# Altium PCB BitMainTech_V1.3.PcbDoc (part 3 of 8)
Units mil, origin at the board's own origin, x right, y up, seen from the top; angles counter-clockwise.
Board outline 9842.52 x 6082.68 mil, 4 copper layers (Top Layer, Mid-Layer 1, Mid-Layer 2, Bottom Layer); 987 components, 282 nets, 3694 pads, 3174 vias.
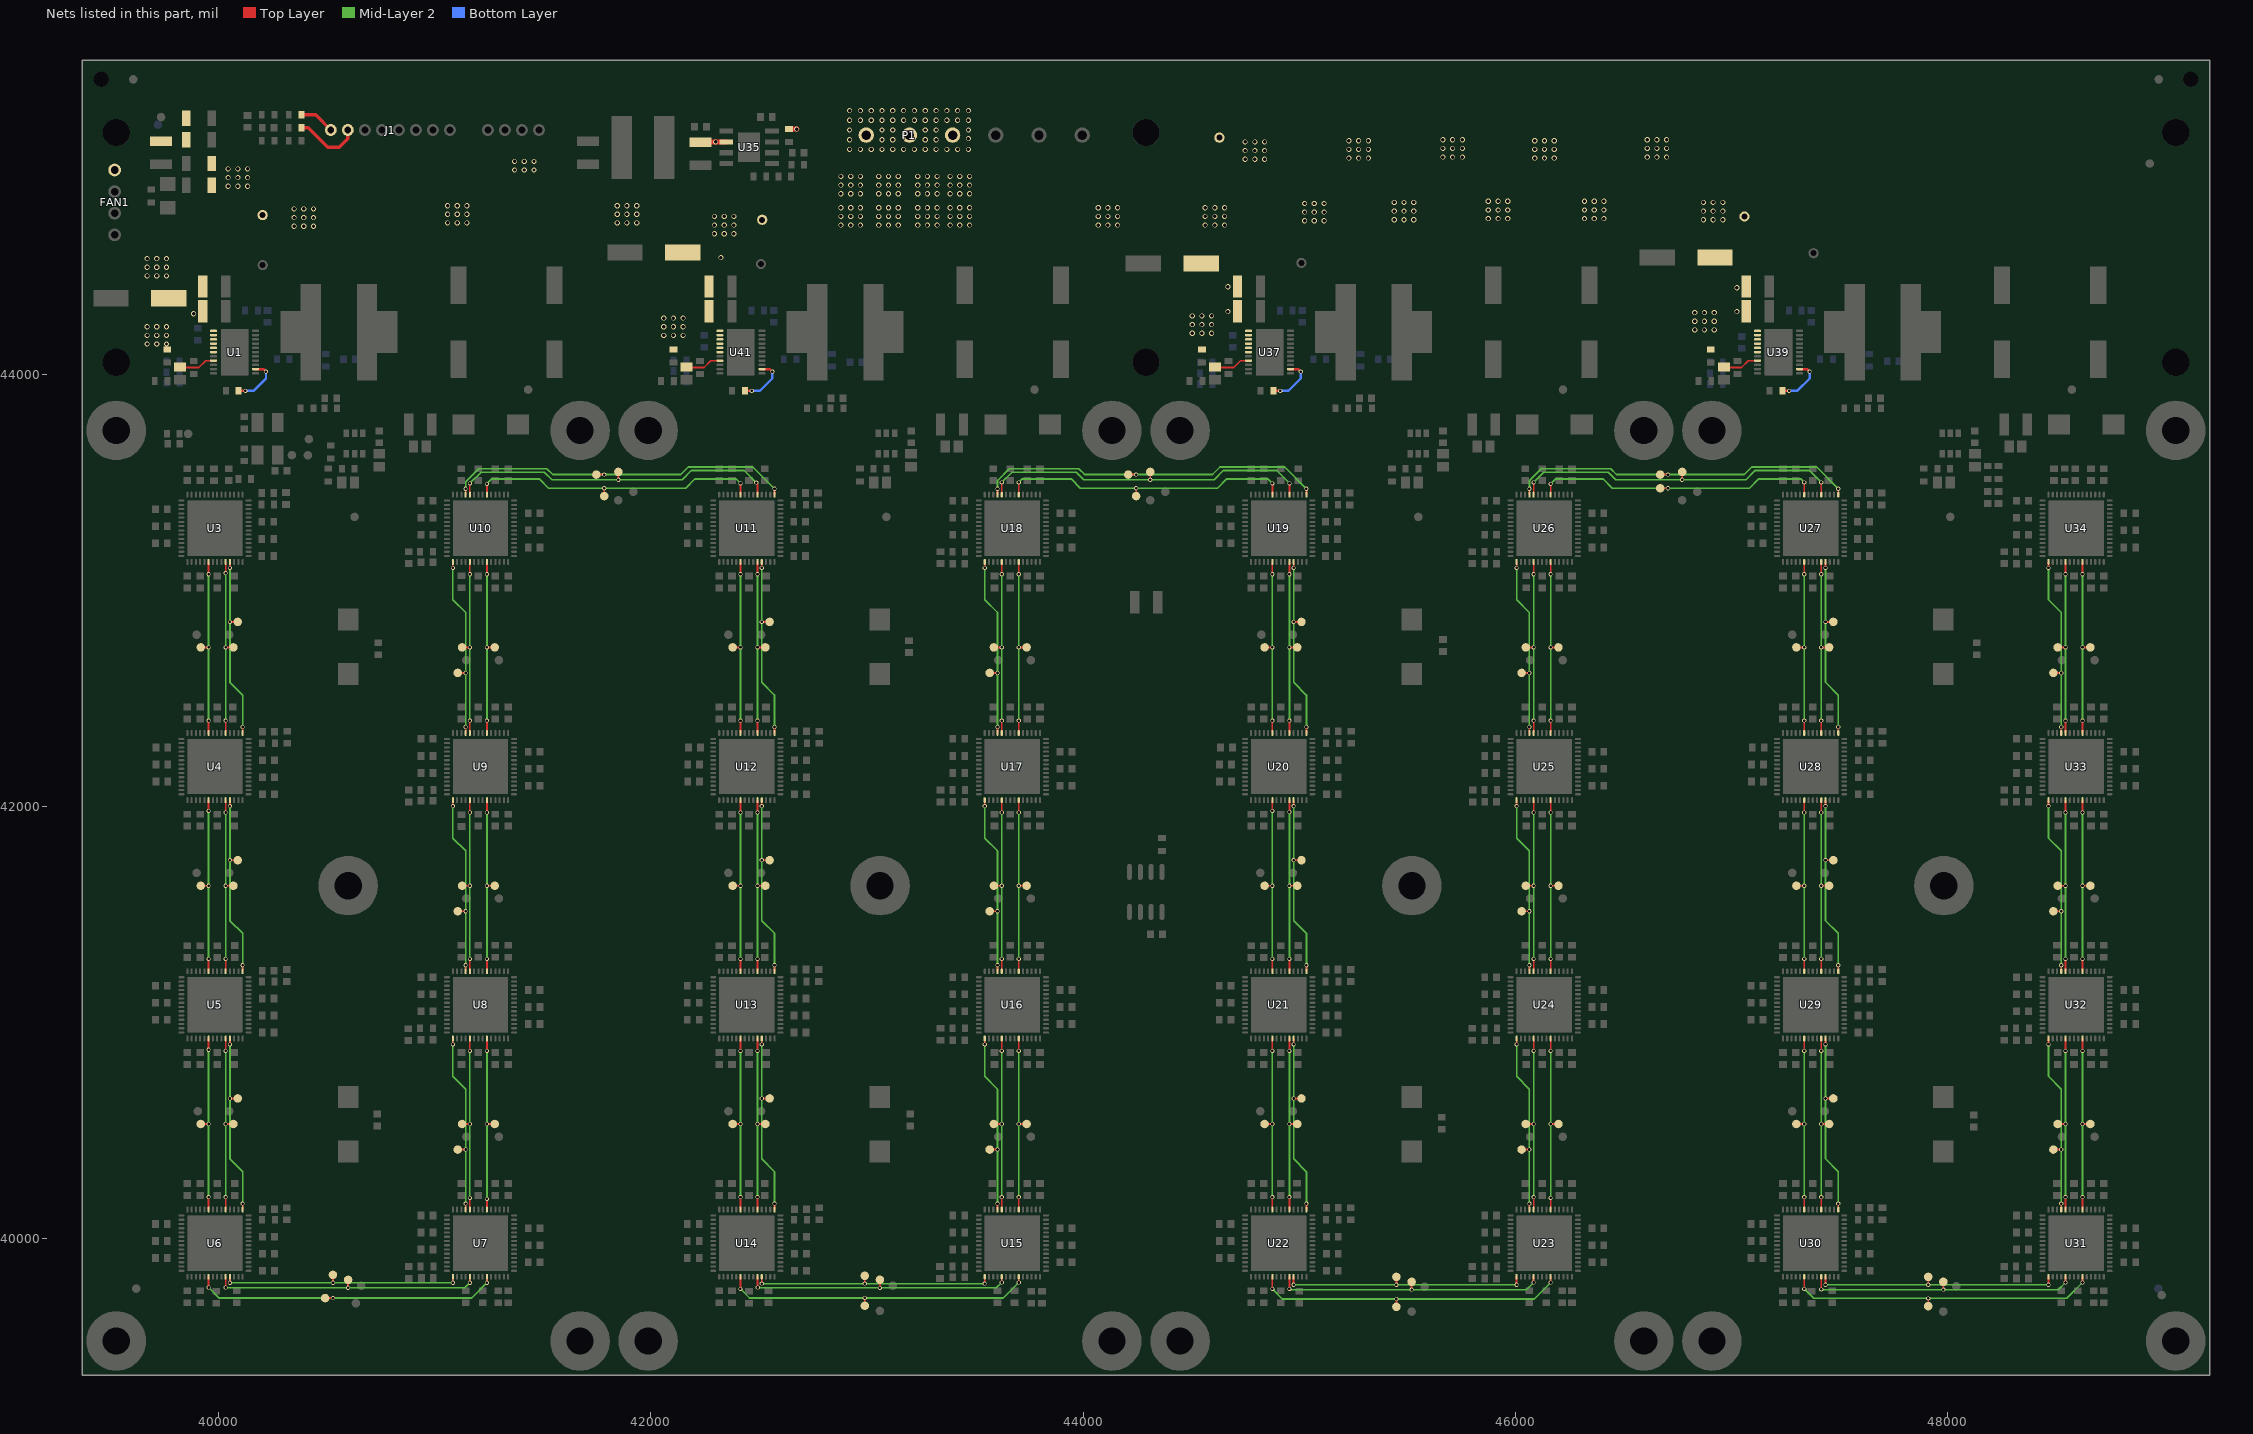
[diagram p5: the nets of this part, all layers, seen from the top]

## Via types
v1: diameter 19, hole 12, Top Layer to Bottom Layer, 1347 vias
v2: diameter 25.98, hole 12.99, Top Layer to Bottom Layer, 800 vias
v3: diameter 24, hole 16, Top Layer to Bottom Layer, 778 vias
v4: diameter 50, hole 28, Top Layer to Bottom Layer, 160 vias
v5: diameter 19.68, hole 11.81, Top Layer to Bottom Layer, 84 vias
v6: diameter 26, hole 18, Top Layer to Bottom Layer, 5 vias

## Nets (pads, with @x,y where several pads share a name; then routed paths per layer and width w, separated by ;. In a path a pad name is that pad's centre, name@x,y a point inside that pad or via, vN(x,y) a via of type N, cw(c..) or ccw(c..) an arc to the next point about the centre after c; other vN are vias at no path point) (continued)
+12V: C5.1 C6.1 C7.1 C548.2 C553.1 C554.1 C568.1 C569.1 C570.1 C584.1 C585.1 C586.1 C600.1 C606.1 C607.1 C608.1 C609.1 FB33.2 FB34.2 P1.1 P1.2 P1.3 R2.1 R22.2 R37.1 R51.1 R65.1 TP2.1 TP165.1 TP169.1 TP173.1 U1.12 U1.13 U1.14 U1.15 U1.16 U1.17 U1.19 U35.2 U37.12 U37.13 U37.14 U37.15 U37.16 U37.17 U37.19 U39.12 U39.13 U39.14 U39.15 U39.16 U39.17 U39.19 U41.12 U41.13 U41.14 U41.15 U41.16 U41.17 U41.19 | length 821.5
  Top Layer w8: C7.1@39822.83,44031.5 39909.5,44031.5 39940.99,44062.99 U1.19@39977.56,44062.99 ; C554.1@42165.35,44031.5 42246.58,44031.5 ; 42246.54,44031.54 42277.99,44062.99 U41.19@42320.08,44062.99 ; C570.1@44610.24,44031.5 44696.9,44031.5 44728.39,44062.99 U37.19@44764.96,44062.99 ; C586.1@46964.57,44031.5 47046.5,44031.5 47077.99,44062.99 U39.19@47119.29,44062.99
  Top Layer w24: C548.2@42232.09,45075 U35.2@42347.48,45075
  Top Layer w25: R22.2@42640,45134.53 v3(42675,45134.53)
  other v3: 39670,44140 39715,44140 39760,44140 39670,44180 39715,44180 39760,44180 42060,44180 42105,44180 42150,44180 44505,44190 44550,44190 44595,44190 46830,44205 46875,44205 46920,44205 39670,44220 39715,44220 39760,44220 42060,44220 42105,44220 42150,44220 44505,44230 44550,44230 44595,44230 46830,44245 46875,44245 46920,44245 42060,44260 42105,44260 42150,44260 44505,44270 44550,44270 44595,44270 39885,44280 46830,44285 46875,44285 46920,44285 44670,44290 47025,44290 47025,44400 44670,44405 39670,44455 39715,44455 39760,44455 39670,44495 39715,44495 39760,44495 39670,44535 39715,44535 39760,44535 42325,44540 42295,44650 42340,44650 42385,44650 40350,44685 40395,44685 40440,44685 42295,44690 42340,44690 42385,44690 42880,44690 42925,44690 42970,44690 43055,44690 43100,44690 43145,44690 43235,44690 43280,44690 43325,44690 43385,44690 43430,44690 43475,44690 44070,44690 44115,44690 44160,44690 44565,44690 44610,44690 44655,44690 41060,44700 41105,44700 41150,44700 41845,44700 41890,44700 41935,44700 45025,44710 45070,44710 45115,44710 45440,44715 45485,44715 45530,44715 46870,44715 46915,44715 46960,44715 45875,44720 45920,44720 45965,44720 46320,44720 46365,44720 46410,44720 40350,44725 40395,44725 40440,44725 42295,44730 42340,44730 42385,44730 42880,44730 42925,44730 42970,44730 43055,44730 43100,44730 43145,44730 43235,44730 43280,44730 43325,44730 43385,44730 43430,44730 43475,44730 44070,44730 44115,44730 44160,44730 44565,44730 44610,44730 44655,44730 41060,44740 41105,44740 41150,44740 41845,44740 41890,44740 41935,44740 45025,44750 45070,44750 45115,44750 45440,44755 45485,44755 45530,44755 46870,44755 46915,44755 46960,44755 45875,44760 45920,44760 45965,44760 46320,44760 46365,44760 46410,44760 40350,44765 40395,44765 40440,44765 42880,44770 42925,44770 42970,44770 43055,44770 43100,44770 43145,44770 43235,44770 43280,44770 43325,44770 43385,44770 43430,44770 43475,44770 44070,44770 44115,44770 44160,44770 44565,44770 44610,44770 44655,44770 41060,44780 41105,44780 41150,44780 41845,44780 41890,44780 41935,44780 45025,44790 45070,44790 45115,44790 45440,44795 45485,44795 45530,44795 46870,44795 46915,44795 46960,44795 45875,44800 45920,44800 45965,44800 46320,44800 46365,44800 46410,44800 42880,44835 42925,44835 42970,44835 43055,44835 43100,44835 43145,44835 43235,44835 43280,44835 43325,44835 43385,44835 43430,44835 43475,44835 40045,44870 40090,44870 40135,44870 42880,44875 42925,44875 42970,44875 43055,44875 43100,44875 43145,44875 43235,44875 43280,44875 43325,44875 43385,44875 43430,44875 43475,44875 40045,44910 40090,44910 40135,44910 42880,44915 42925,44915 42970,44915 43055,44915 43100,44915 43145,44915 43235,44915 43280,44915 43325,44915 43385,44915 43430,44915 43475,44915 41370,44945 41415,44945 41460,44945 40045,44950 40090,44950 40135,44950 41370,44985 41415,44985 41460,44985 44750,44995 44795,44995 44840,44995 45230,45000 45275,45000 45320,45000 46090,45000 46135,45000 46180,45000 45665,45005 45710,45005 45755,45005 46610,45005 46655,45005 46700,45005 44750,45035 44795,45035 44840,45035 42920,45040 42970,45040 43020,45040 43070,45040 43120,45040 43170,45040 43220,45040 43270,45040 43320,45040 43370,45040 43420,45040 43470,45040 45230,45040 45275,45040 45320,45040 46090,45040 46135,45040 46180,45040 45665,45045 45710,45045 45755,45045 46610,45045 46655,45045 46700,45045 42300,45075 44750,45075 44795,45075 44840,45075 45230,45080 45275,45080 45320,45080 46090,45080 46135,45080 46180,45080 42920,45085 43070,45085 43120,45085 43270,45085 43320,45085 45665,45085 45710,45085 45755,45085 46610,45085 46655,45085 46700,45085 43470,45090 42920,45130 43070,45130 43120,45130 43270,45130 43320,45130 43470,45130 42920,45175 42970,45175 43020,45175 43070,45175 43120,45175 43170,45175 43220,45175 43270,45175 43320,45175 43370,45175 43420,45175 43470,45175 42920,45220 42970,45220 43020,45220 43070,45220 43120,45220 43170,45220 43220,45220 43270,45220 43320,45220 43370,45220 43420,45220 43470,45220
BO1: TP5.1 U3.34 U4.9 | length 827.5
  Top Layer w8: TP5.1@39918.54,42736.22 v1(39954.72,42736.22) ; U4.9@39954.72,42340.55 v1(39954.72,42397.69) ; v1(39954.72,43074.75) U3.34@39954.72,43131.89
  Mid-Layer 2 w8: v1(39954.72,42397.69) v1(39954.72,43074.75)
BO2: TP6.1 U4.34 U5.9 | length 827.5
  Top Layer w8: TP6.1@39918.54,41633.86 v1(39954.72,41633.86) ; U5.9@39954.72,41238.19 v1(39954.72,41295.33) ; v1(39954.72,41980) U4.34@39954.72,42029.53
  Mid-Layer 2 w8: v1(39954.72,41295.33) v1(39954.72,41980)
BO3: TP7.1 U5.34 U6.9 | length 827.5
  Top Layer w8: TP7.1@39918.54,40531.5 v1(39954.72,40531.5) ; U6.9@39954.72,40135.83 v1(39954.72,40192.97) ; v1(39954.72,40875) U5.34@39954.72,40927.17
  Mid-Layer 2 w8: v1(39954.72,40192.97) v1(39954.72,40875)
BO4: TP8.1 U6.34 U7.9 | length 1450.8
  Top Layer w8: v1(39954.72,39775) U6.34@39954.72,39824.8 ; TP8.1@40493.82,39726 v1(40530,39726) ; v1(41242.13,39797.24) U7.9@41242.13,39824.8
  Mid-Layer 2 w8: v1(39954.72,39775) 40003.72,39726 41170.88,39726 v1(41242.13,39797.24)
BO5: TP29.1 U7.34 U8.9 | length 827.5
  Top Layer w8: U7.34@41242.13,40135.83 v1(41242.13,40185) ; v1(41242.13,40531.5) TP29.1@41278.31,40531.5 ; v1(41242.13,40870.02) U8.9@41242.13,40927.17
  Mid-Layer 2 w8: v1(41242.13,40185) v1(41242.13,40870.02)
BO6: TP30.1 U8.34 U9.9 | length 827.5
  Top Layer w8: U8.34@41242.13,41238.19 v1(41242.13,41295.33) ; v1(41242.13,41633.86) TP30.1@41278.31,41633.86 ; v1(41242.13,41972.39) U9.9@41242.13,42029.53
  Mid-Layer 2 w8: v1(41242.13,41295.33) v1(41242.13,41972.39)
BO7: TP31.1 U9.34 U10.9 | length 827.5
  Top Layer w8: U9.34@41242.13,42340.55 v1(41242.13,42397.69) ; v1(41242.13,42736.22) TP31.1@41278.31,42736.22 ; v1(41242.13,43074.75) U10.9@41242.13,43131.89
  Mid-Layer 2 w8: v1(41242.13,42397.69) v1(41242.13,43074.75)
BO8: TP32.1 U10.34 U11.9 | length 1365.1
  Top Layer w8: U10.34@41242.13,43442.91 v1(41242.13,43492.8) ; TP32.1@41785,43436.63 v1(41785,43472.81) ; U11.9@42415.35,43442.91 v1(42415.35,43495)
  Mid-Layer 2 w8: v1(41242.13,43492.8) 41265.07,43515.75 41484.25,43515.75 41527.19,43472.81 42161.79,43472.81 42204.72,43515.75 42394.61,43515.75 v1(42415.35,43495)
BO9: TP49.1 U11.34 U12.9 | length 827.5
  Top Layer w8: TP49.1@42379.17,42736.22 v1(42415.35,42736.22) ; U12.9@42415.35,42340.55 v1(42415.35,42397.69) ; v1(42415.35,43074.75) U11.34@42415.35,43131.89
  Mid-Layer 2 w8: v1(42415.35,42397.69) v1(42415.35,43074.75)
BO10: TP50.1 U12.34 U13.9 | length 827.5
  Top Layer w8: TP50.1@42379.17,41633.86 v1(42415.35,41633.86) ; U13.9@42415.35,41238.19 v1(42415.35,41295.33) ; v1(42415.35,41972.39) U12.34@42415.35,42029.53
  Mid-Layer 2 w8: v1(42415.35,41295.33) v1(42415.35,41972.39)
BO11: TP51.1 U13.34 U14.9 | length 827.5
  Top Layer w8: TP51.1@42379.17,40531.5 v1(42415.35,40531.5) ; U14.9@42415.35,40135.83 v1(42415.35,40192.97) ; v1(42415.35,40870.02) U13.34@42415.35,40927.17
  Mid-Layer 2 w8: v1(42415.35,40192.97) v1(42415.35,40870.02)
BO12: TP52.1 U14.34 U15.9 | length 1455.1
  Top Layer w8: v1(42415.17,39768.46) U14.34@42415.17,39825.61 ; TP52.1@42990.44,39690.62 v1(42990.44,39726.8) ; v1(43702.57,39798.05) U15.9@43702.57,39825.61
  Mid-Layer 2 w8: v1(42415.17,39768.46) 42456.83,39726.8 43631.32,39726.8 v1(43702.57,39798.05)
BO13: TP70.1 U15.34 U16.9 | length 827.5
  Top Layer w8: U15.34@43702.76,40135.83 v1(43702.76,40192.97) ; v1(43702.76,40531.5) TP70.1@43738.94,40531.5 ; v1(43702.76,40870.02) U16.9@43702.76,40927.17
  Mid-Layer 2 w8: v1(43702.76,40192.97) v1(43702.76,40870.02)
BO14: TP71.1 U16.34 U17.9 | length 827.5
  Top Layer w8: U16.34@43702.76,41238.19 v1(43702.76,41295.33) ; v1(43702.76,41633.86) TP71.1@43738.94,41633.86 ; v1(43702.76,41972.39) U17.9@43702.76,42029.53
  Mid-Layer 2 w8: v1(43702.76,41295.33) v1(43702.76,41972.39)
BO15: TP72.1 U17.34 U18.9 | length 827.5
  Top Layer w8: U17.34@43702.76,42340.55 v1(43702.76,42397.69) ; v1(43702.76,42736.22) TP72.1@43738.94,42736.22 ; v1(43702.76,43074.75) U18.9@43702.76,43131.89
  Mid-Layer 2 w8: v1(43702.76,42397.69) v1(43702.76,43074.75)
BO16: TP69.1 U18.34 U19.9 | length 1369.3
  Top Layer w8: U18.34@43702.76,43442.91 v1(43702.76,43500.06) ; TP69.1@44245.63,43436.63 v1(44245.63,43472.81) ; U19.9@44876.26,43443.66 v1@44876.26,43495.75
  Mid-Layer 2 w8: v1(43702.76,43500.06) 43718.45,43515.75 43944.88,43515.75 43987.82,43472.81 44622.42,43472.81 44665.35,43515.75 44855.24,43515.75 v1(44875.98,43495)
BO17: TP89.1 U19.34 U20.9 | length 827.5
  Top Layer w8: TP89.1@44839.8,42736.22 v1(44875.98,42736.22) ; U20.9@44875.98,42340.55 v1(44875.98,42397.69) ; v1(44875.98,43074.75) U19.34@44875.98,43131.89
  Mid-Layer 2 w8: v1(44875.98,42397.69) v1(44875.98,43074.75)
BO18: TP90.1 U20.34 U21.9 | length 827.9
  Top Layer w8: TP90.1@44839.8,41633.86 v1(44875.98,41633.86) ; v1@44875,41980 44875.98,41980.98 U20.34@44875.98,42029.53 ; U21.9@44875.98,41238.19 v1(44875.98,41295.33)
  Mid-Layer 2 w8: v1(44875.98,41295.33) v1(44875.98,41980)
BO19: TP91.1 U21.34 U22.9 | length 827.5
  Top Layer w8: TP91.1@44839.8,40531.5 v1(44875.98,40531.5) ; U22.9@44875.98,40135.83 v1(44875.98,40192.97) ; v1(44875.98,40870.02) U21.34@44875.98,40927.17
  Mid-Layer 2 w8: v1(44875.98,40192.97) v1(44875.98,40870.02)
BO20: TP92.1 U22.34 U23.9 | length 1459.2
  Top Layer w8: v1(44875.8,39768.46) U22.34@44875.8,39825.61 ; TP92.1@45450,39685.62 v1(45450,39721.8) ; v1(46163.2,39798.05) U23.9@46163.2,39825.61
  Mid-Layer 2 w8: v1(44875.8,39768.46) 44922.46,39721.8 46086.95,39721.8 46091.95,39726.8 v1(46163.2,39798.05)
BO21: TP109.1 U23.34 U24.9 | length 827.5
  Top Layer w8: U23.34@46163.39,40135.83 v1(46163.39,40190) ; v1(46163.39,40531.5) TP109.1@46199.57,40531.5 ; v1(46163.39,40870.02) U24.9@46163.39,40927.17
  Mid-Layer 2 w8: v1(46163.39,40190) v1(46163.39,40870.02)
BO22: TP110.1 U24.34 U25.9 | length 827.5
  Top Layer w8: U24.34@46163.39,41238.19 v1(46163.39,41295.33) ; v1(46163.39,41633.86) TP110.1@46199.57,41633.86 ; v1(46163.39,41972.39) U25.9@46163.39,42029.53
  Mid-Layer 2 w8: v1(46163.39,41295.33) v1(46163.39,41972.39)
BO23: TP111.1 U25.34 U26.9 | length 827.5
  Top Layer w8: U25.34@46163.39,42340.55 v1(46163.39,42397.69) ; v1(46163.39,42736.22) TP111.1@46199.57,42736.22 ; v1(46163.39,43074.75) U26.9@46163.39,43131.89
  Mid-Layer 2 w8: v1(46163.39,42397.69) v1(46163.39,43074.75)
BO24: TP112.1 U26.34 U27.9 | length 1367
  Top Layer w8: U26.34@46163.39,43442.91 v1(46163.39,43492.8) ; TP112.1@46670.08,43472.81 v1(46706.26,43472.81) ; U27.9@47336.61,43442.91 v1(47336.61,43500.06)
  Mid-Layer 2 w8: v1(46163.39,43492.8) 46186.33,43515.75 46405.51,43515.75 46448.45,43472.81 47083.05,43472.81 47125.98,43515.75 47319.54,43515.75 v1@47335.46,43499.83
BO25: TP4.1 U27.34 U28.9 | length 827.5
  Top Layer w8: TP4.1@47300.43,42736.22 v1(47336.61,42736.22) ; U28.9@47336.61,42340.55 v1(47336.61,42397.69) ; v1(47336.61,43074.75) U27.34@47336.61,43131.89
  Mid-Layer 2 w8: v1(47336.61,42397.69) v1(47336.61,43074.75)
BO26: TP130.1 U28.34 U29.9 | length 827.5
  Top Layer w8: TP130.1@47300.43,41633.86 v1(47336.61,41633.86) ; U29.9@47336.61,41238.19 v1(47336.61,41295.33) ; v1(47336.61,41972.39) U28.34@47336.61,42029.53
  Mid-Layer 2 w8: v1(47336.61,41295.33) v1(47336.61,41972.39)
BO27: TP131.1 U29.34 U30.9 | length 827.5
  Top Layer w8: TP131.1@47300.43,40531.5 v1(47336.61,40531.5) ; U30.9@47336.61,40135.83 v1(47336.61,40192.97) ; v1(47336.61,40870.02) U29.34@47336.61,40927.17
  Mid-Layer 2 w8: v1(47336.61,40192.97) v1(47336.61,40870.02)
BO28: TP132.1 U30.34 U31.9 | length 1459.1
  Top Layer w8: v1(47336.43,39768.46) U30.34@47336.43,39824.61 ; TP132.1@47910,39688.82 v1(47910,39725) ; v1(48623.83,39798.05) U31.9@48623.83,39825.61
  Mid-Layer 2 w8: v1@47332.93,39768.46 v1(47336.43,39768.46) 47379.89,39725 48550.78,39725 v1(48623.83,39798.05)
BO29: TP149.1 U31.34 U32.9 | length 827.5
  Top Layer w8: U31.34@48624.02,40135.83 v1(48624.02,40192.97) ; v1(48624.02,40531.5) TP149.1@48660.2,40531.5 ; v1(48624.02,40870.02) U32.9@48624.02,40927.17
  Mid-Layer 2 w8: v1(48624.02,40192.97) v1(48624.02,40870.02)
BO30: TP150.1 U32.34 U33.9 | length 827.5
  Top Layer w8: U32.34@48624.02,41238.19 v1(48624.02,41295.33) ; v1(48624.02,41633.86) TP150.1@48660.2,41633.86 ; v1(48624.02,41972.39) U33.9@48624.02,42029.53
  Mid-Layer 2 w8: v1(48624.02,41295.33) v1(48624.02,41972.39)
BO31: TP151.1 U33.34 U34.9 | length 827.5
  Top Layer w8: U33.34@48624.02,42340.55 v1(48624.02,42397.69) ; v1(48624.02,42736.22) TP151.1@48660.2,42736.22 ; v1(48624.02,43074.75) U34.9@48624.02,43131.89
  Mid-Layer 2 w8: v1(48624.02,42397.69) v1(48624.02,43074.75)
CLK1: TP18.1 U3.39 U4.1 | length 852
  Top Layer w8: v1(40053.15,42854.33) TP18.1@40089.33,42854.33 ; v1(40053.15,43104.33) U3.39@40053.15,43131.89 ; U4.1@40112.2,42340.55 v1(40112.2,42368.11)
  Mid-Layer 2 w8: v1(40053.15,43104.33) v1(40053.15,42854.33) 40053.15,42574.85 40112.2,42515.8 v1(40112.2,42368.11)
CLK2: TP20.1 U4.39 U5.1 | length 907.1
  Top Layer w8: v1(40053.15,41751.97) TP20.1@40089.33,41751.97 ; v1(40053.15,42001.97) U4.39@40053.15,42029.53 v1(40053.15,42001.97) ; U5.1@40112.2,41238.19 v1(40112.2,41265.75) U5.1@40112.2,41238.19
  Mid-Layer 2 w8: v1(40053.15,42001.97) 40053.15,41472.49 40112.2,41413.43 v1(40112.2,41265.75)
CLK3: TP22.1 U5.39 U6.1 | length 907.1
  Top Layer w8: v1(40053.15,40649.61) TP22.1@40089.33,40649.61 ; v1(40053.15,40899.61) U5.39@40053.15,40927.17 v1(40053.15,40899.61) ; U6.1@40112.2,40135.83 v1(40112.2,40163.39) U6.1@40112.2,40135.83
  Mid-Layer 2 w8: v1(40053.15,40899.61) 40053.15,40370.13 40112.2,40311.07 v1(40112.2,40163.39)
CLK4: TP24.1 U6.39 U7.1 | length 1122.8
  Top Layer w8: v1(40053.15,39797.24) U6.39@40053.15,39824.8 ; v1(40530,39797.24) TP24.1@40530,39833.43 ; v1(41084.65,39797.24) U7.1@41084.65,39824.8
  Mid-Layer 2 w8: v1(40053.15,39797.24) v1(41084.65,39797.24)
CLK5: TP42.1 U7.39 U8.1 | length 907.1
  Top Layer w8: TP42.1@41107.52,40413.39 v1(41143.7,40413.39) ; v1(41084.65,40899.61) U8.1@41084.65,40927.17 v1(41084.65,40899.61) ; U7.39@41143.7,40135.83 v1(41143.7,40163.39) U7.39@41143.7,40135.83
  Mid-Layer 2 w8: v1(41084.65,40899.61) 41084.65,40751.92 41143.7,40692.87 v1(41143.7,40163.39)
CLK6: TP44.1 U8.39 U9.1 | length 907.1
  Top Layer w8: TP44.1@41107.52,41515.75 v1(41143.7,41515.75) ; v1(41084.65,42001.97) U9.1@41084.65,42029.53 v1(41084.65,42001.97) ; U8.39@41143.7,41238.19 v1(41143.7,41265.75) U8.39@41143.7,41238.19
  Mid-Layer 2 w8: v1(41084.65,42001.97) 41084.65,41854.28 41143.7,41795.23 v1(41143.7,41265.75)
CLK7: TP46.1 U9.39 U10.1 | length 907.1
  Top Layer w8: TP46.1@41107.52,42618.11 v1(41143.7,42618.11) ; v1(41084.65,43104.33) U10.1@41084.65,43131.89 v1(41084.65,43104.33) ; U9.39@41143.7,42340.55 v1(41143.7,42368.11) U9.39@41143.7,42340.55
  Mid-Layer 2 w8: v1(41084.65,43104.33) 41084.65,42956.65 41143.7,42897.59 v1(41143.7,42368.11)
CLK8: TP48.1 U10.39 U11.1 | length 1645
  Top Layer w8: U10.39@41143.7,43442.91 v1(41143.7,43470.47) ; TP48.1@41748.82,43536 v1(41785,43536) ; U11.1@42572.83,43442.91 v1(42572.83,43470.47)
  Mid-Layer 2 w8: v1(41143.7,43470.47) 41143.89,43470.66 41143.89,43503.08 41203.8,43562.99 41519.69,43562.99 41546.68,43536 42138.36,43536 42173.23,43570.87 42472.44,43570.87 v1(42572.83,43470.47)
CLK9: TP62.1 U11.39 U12.1 | length 879.5
  Top Layer w8: v1(42513.78,42854.33) TP62.1@42549.96,42854.33 ; U12.1@42572.83,42340.55 v1(42572.83,42368.11) ; v1(42513.78,43104.33) U11.39@42513.78,43131.89 v1(42513.78,43104.33)
  Mid-Layer 2 w8: v1(42513.78,43104.33) 42513.78,42574.85 42572.83,42515.8 v1(42572.83,42368.11)
CLK10: TP64.1 U12.39 U13.1 | length 907.1
  Top Layer w8: v1(42513.78,41751.97) TP64.1@42549.96,41751.97 ; v1(42513.78,42001.97) U12.39@42513.78,42029.53 v1(42513.78,42001.97) ; U13.1@42572.83,41238.19 v1(42572.83,41265.75) U13.1@42572.83,41238.19
  Mid-Layer 2 w8: v1(42513.78,42001.97) 42513.78,41472.49 42572.83,41413.43 v1(42572.83,41265.75)
CLK11: TP66.1 U13.39 U14.1 | length 907.1
  Top Layer w8: v1(42513.78,40649.61) TP66.1@42549.96,40649.61 ; v1(42513.78,40899.61) U13.39@42513.78,40927.17 v1(42513.78,40899.61) ; U14.1@42572.83,40135.83 v1(42572.83,40163.39) U14.1@42572.83,40135.83
  Mid-Layer 2 w8: v1(42513.78,40899.61) 42513.78,40370.13 42572.83,40311.07 v1(42572.83,40163.39)
CLK12: TP68.1 U14.39 U15.1 | length 1132.8
  Top Layer w8: v1(42513.59,39793.05) U14.39@42513.59,39825.61 ; v1(42990,39793.05) TP68.1@42990,39829.23 ; v1(43545.09,39793.05) U15.1@43545.09,39825.61
  Mid-Layer 2 w8: v1(42513.59,39793.05) v1(43545.09,39793.05)
CLK13: TP84.1 U15.39 U16.1 | length 879.5
  Top Layer w8: TP84.1@43568.15,40413.39 v1(43604.33,40413.39) ; U15.39@43604.33,40135.83 v1(43604.33,40163.39) ; v1(43545.28,40899.61) U16.1@43545.28,40927.17 v1(43545.28,40899.61)
  Mid-Layer 2 w8: v1(43545.28,40899.61) 43545.28,40751.92 43604.33,40692.87 v1(43604.33,40163.39)
CLK14: TP86.1 U16.39 U17.1 | length 907.1
  Top Layer w8: TP86.1@43568.15,41515.75 v1(43604.33,41515.75) ; v1(43545.28,42001.97) U17.1@43545.28,42029.53 v1(43545.28,42001.97) ; U16.39@43604.33,41238.19 v1(43604.33,41265.75) U16.39@43604.33,41238.19
  Mid-Layer 2 w8: v1(43545.28,42001.97) 43545.28,41854.28 43604.33,41795.23 v1(43604.33,41265.75)
CLK15: TP88.1 U17.39 U18.1 | length 907.1
  Top Layer w8: TP88.1@43568.15,42618.11 v1(43604.33,42618.11) ; v1(43545.28,43104.33) U18.1@43545.28,43131.89 v1(43545.28,43104.33) ; U17.39@43604.33,42340.55 v1(43604.33,42368.11) U17.39@43604.33,42340.55
  Mid-Layer 2 w8: v1(43545.28,43104.33) 43545.28,42956.65 43604.33,42897.59 v1(43604.33,42368.11)
CLK16: TP82.1 U18.39 U19.1 | length 1647.7
  Top Layer w8: U18.39@43604.33,43442.91 v1(43604.33,43470.47) ; TP82.1@44209.45,43536 v1(44245.63,43536) ; U19.1@45033.74,43443.66 v1@45033.74,43471.22
  Mid-Layer 2 w8: v1@43604.52,43470.66 43604.52,43508.13 43659.37,43562.99 43980.32,43562.99 44007.31,43536 44598.99,43536 44633.86,43570.87 44933.07,43570.87 v1(45033.46,43470.47)
CLK17: TP102.1 U19.39 U20.1 | length 907.1
  Top Layer w8: v1(44974.41,42854.33) TP102.1@45010.59,42854.33 ; v1(44974.41,43104.33) U19.39@44974.41,43131.89 v1(44974.41,43104.33) ; U20.1@45033.46,42340.55 v1(45033.46,42368.11) U20.1@45033.46,42340.55
  Mid-Layer 2 w8: v1(44974.41,43104.33) 44974.41,42574.85 45033.46,42515.8 v1(45033.46,42368.11)
CLK18: TP104.1 U20.39 U21.1 | length 907.1
  Top Layer w8: v1(44974.41,41751.97) TP104.1@45010.59,41751.97 ; v1(44974.41,42001.97) U20.39@44974.41,42029.53 v1(44974.41,42001.97) ; U21.1@45033.46,41238.19 v1(45033.46,41265.75) U21.1@45033.46,41238.19
  Mid-Layer 2 w8: v1(44974.41,42001.97) 44974.41,41472.49 45033.46,41413.43 v1(45033.46,41265.75)
CLK19: TP106.1 U21.39 U22.1 | length 907.1
  Top Layer w8: v1(44974.41,40649.61) TP106.1@45010.59,40649.61 ; v1(44974.41,40899.61) U21.39@44974.41,40927.17 v1(44974.41,40899.61) ; U22.1@45033.46,40135.83 v1(45033.46,40163.39) U22.1@45033.46,40135.83
  Mid-Layer 2 w8: v1(44974.41,40899.61) 44974.41,40370.13 45033.46,40311.07 v1(45033.46,40163.39)
CLK20: TP108.1 U22.39 U23.1 | length 1142.8
  Top Layer w8: v1(44974.22,39788.05) U22.39@44974.22,39825.61 ; v1(45450,39788.05) TP108.1@45450,39824.23 ; v1(46005.72,39788.05) U23.1@46005.72,39825.61
  Mid-Layer 2 w8: v1(44974.22,39788.05) v1(46005.72,39788.05)
CLK21: TP122.1 U23.39 U24.1 | length 907.1
  Top Layer w8: TP122.1@46028.78,40413.39 v1(46064.96,40413.39) ; v1(46005.91,40899.61) U24.1@46005.91,40927.17 v1(46005.91,40899.61) ; U23.39@46064.96,40135.83 v1(46064.96,40163.39) U23.39@46064.96,40135.83
  Mid-Layer 2 w8: v1(46005.91,40899.61) 46005.91,40751.92 46064.96,40692.87 v1(46064.96,40163.39)
CLK22: TP124.1 U24.39 U25.1 | length 907.1
  Top Layer w8: TP124.1@46028.78,41515.75 v1(46064.96,41515.75) ; v1(46005.91,42001.97) U25.1@46005.91,42029.53 v1(46005.91,42001.97) ; U24.39@46064.96,41238.19 v1(46064.96,41265.75) U24.39@46064.96,41238.19
  Mid-Layer 2 w8: v1(46005.91,42001.97) 46005.91,41854.28 46064.96,41795.23 v1(46064.96,41265.75)
CLK23: TP126.1 U25.39 U26.1 | length 907.1
  Top Layer w8: TP126.1@46028.78,42618.11 v1(46064.96,42618.11) ; v1(46005.91,43104.33) U26.1@46005.91,43131.89 v1(46005.91,43104.33) ; U25.39@46064.96,42340.55 v1(46064.96,42368.11) U25.39@46064.96,42340.55
  Mid-Layer 2 w8: v1(46005.91,43104.33) 46005.91,42956.65 46064.96,42897.59 v1(46064.96,42368.11)
CLK24: TP128.1 U26.39 U27.1 | length 1647.7
  Top Layer w8: U26.39@46064.96,43442.91 v1(46064.96,43470.47) ; TP128.1@46670.08,43536 v1(46706.26,43536) ; U27.1@47494.09,43442.91 v1(47494.09,43470.47)
  Mid-Layer 2 w8: v1@46065.15,43470.66 46065.15,43508.13 46120,43562.99 46440.94,43562.99 46467.94,43536 47059.62,43536 47094.49,43570.87 47393.7,43570.87 v1(47494.09,43470.47)
CLK25: TP142.1 U27.39 U28.1 | length 907.1
  Top Layer w8: v1(47435.04,42854.33) TP142.1@47471.22,42854.33 ; v1(47435.04,43104.33) U27.39@47435.04,43131.89 v1(47435.04,43104.33) ; U28.1@47494.09,42340.55 v1(47494.09,42368.11) U28.1@47494.09,42340.55
  Mid-Layer 2 w8: v1(47435.04,43104.33) 47435.04,42574.85 47494.09,42515.8 v1(47494.09,42368.11)
CLK26: TP144.1 U28.39 U29.1 | length 907.1
  Top Layer w8: v1(47435.04,41751.97) TP144.1@47471.22,41751.97 ; v1(47435.04,42001.97) U28.39@47435.04,42029.53 v1(47435.04,42001.97) ; U29.1@47494.09,41238.19 v1(47494.09,41265.75) U29.1@47494.09,41238.19
  Mid-Layer 2 w8: v1(47435.04,42001.97) 47435.04,41472.49 47494.09,41413.43 v1(47494.09,41265.75)
CLK27: TP146.1 U29.39 U30.1 | length 907.1
  Top Layer w8: v1(47435.04,40649.61) TP146.1@47471.22,40649.61 ; v1(47435.04,40899.61) U29.39@47435.04,40927.17 v1(47435.04,40899.61) ; U30.1@47494.09,40135.83 v1(47494.09,40163.39) U30.1@47494.09,40135.83
  Mid-Layer 2 w8: v1(47435.04,40899.61) 47435.04,40370.13 47494.09,40311.07 v1(47494.09,40163.39)
CLK28: TP148.1 U30.39 U31.1 | length 1142.8
  Top Layer w8: v1(47434.85,39788.05) U30.39@47434.85,39825.61 ; v1(47910,39788.05) TP148.1@47910,39824.23 ; v1(48466.35,39788.05) U31.1@48466.35,39825.61
  Mid-Layer 2 w8: v1(47434.85,39788.05) v1(48466.35,39788.05)
CLK29: TP159.1 U31.39 U32.1 | length 907.1
  Top Layer w8: TP159.1@48489.41,40413.39 v1(48525.59,40413.39) ; v1(48466.54,40899.61) U32.1@48466.54,40927.17 v1(48466.54,40899.61) ; U31.39@48525.59,40135.83 v1(48525.59,40163.39) U31.39@48525.59,40135.83
  Mid-Layer 2 w8: v1(48466.54,40899.61) 48466.54,40751.92 48525.59,40692.87 v1(48525.59,40163.39)
CLK30: TP161.1 U32.39 U33.1 | length 907.1
  Top Layer w8: TP161.1@48489.41,41515.75 v1(48525.59,41515.75) ; v1(48466.54,42001.97) U33.1@48466.54,42029.53 v1(48466.54,42001.97) ; U32.39@48525.59,41238.19 v1(48525.59,41265.75) U32.39@48525.59,41238.19
  Mid-Layer 2 w8: v1(48466.54,42001.97) 48466.54,41854.28 48525.59,41795.23 v1(48525.59,41265.75)
CLK31: TP163.1 U33.39 U34.1 | length 907.1
  Top Layer w8: TP163.1@48489.41,42618.11 v1(48525.59,42618.11) ; v1(48466.54,43104.33) U34.1@48466.54,43131.89 v1(48466.54,43104.33) ; U33.39@48525.59,42340.55 v1(48525.59,42368.11) U33.39@48525.59,42340.55
  Mid-Layer 2 w8: v1(48466.54,43104.33) 48466.54,42956.65 48525.59,42897.59 v1(48525.59,42368.11)
CO1: TP9.1 U3.38 U4.5 | length 827.5
  Top Layer w8: U4.5@40033.46,42340.55 v1(40033.46,42397.69) ; v1(40033.46,42736.22) TP9.1@40069.65,42736.22 ; v1(40033.46,43080) U3.38@40033.46,43131.89
  Mid-Layer 2 w8: v1(40033.46,42397.69) v1(40033.46,43080)
CO2: TP11.1 U4.38 U5.5 | length 827.5
  Top Layer w8: U5.5@40033.46,41238.19 v1(40033.47,41295.33) ; v1(40033.46,41633.86) TP11.1@40069.65,41633.86 ; v1(40033.46,41972.39) U4.38@40033.46,42029.53
  Mid-Layer 2 w8: v1(40033.47,41295.33) v1(40033.46,41972.39)
CO3: TP13.1 U5.38 U6.5 | length 834
  Top Layer w8: U6.5@40033.46,40135.83 v1(40033.46,40192.97) ; v1(40033.46,40531.5) TP13.1@40069.65,40531.5 ; v1(40033.46,40870.02) U5.38@40033.46,40927.17
  Mid-Layer 2 w8: v1@40030,40190 40033.46,40190 v1(40033.46,40870.02)
CO4: TP15.1 U6.38 U7.5 | length 1253.1
  Top Layer w8: v1(40033.46,39775) U6.38@40033.46,39824.8 ; v1(40600,39774) TP15.1@40600,39810.18 ; v1(41163.39,39797.24) U7.5@41163.39,39824.8
  Mid-Layer 2 w8: v1@40033.46,39774 41140.14,39774 v1(41163.39,39797.24)
CO5: TP33.1 U7.38 U8.5 | length 827.5
  Top Layer w8: TP33.1@41127.2,40531.5 v1(41163.39,40531.5) ; U7.38@41163.39,40135.83 v1(41163.39,40190) ; v1(41163.39,40870.02) U8.5@41163.39,40927.17
  Mid-Layer 2 w8: v1(41163.39,40190) v1(41163.39,40870.02)
CO6: TP35.1 U8.38 U9.5 | length 827.5
  Top Layer w8: TP35.1@41127.2,41633.86 v1(41163.39,41633.86) ; U8.38@41163.39,41238.19 v1(41163.39,41295.33) ; v1(41163.39,41972.39) U9.5@41163.39,42029.53
  Mid-Layer 2 w8: v1(41163.39,41295.33) v1(41163.39,41972.39)
CO7: TP37.1 U9.38 U10.5 | length 831.7
  Top Layer w8: TP37.1@41127.2,42736.22 v1(41163.39,42736.22) ; U9.38@41163.39,42340.55 v1(41163.39,42397.69) ; v1(41163.39,43074.75) U10.5@41163.39,43131.89
  Mid-Layer 2 w8: v1(41163.39,42397.69) 41163.39,43076.47 v1@41165.11,43074.75
CO8: TP39.1 U10.38 U11.5 | length 1548.9
  Top Layer w8: U10.38@41163.39,43442.91 v1(41163.39,43495) ; v1(41850.39,43511.81) TP39.1@41850.39,43547.99 ; v1(42488.05,43498.85) 42494.09,43492.8 U11.5@42494.09,43442.91
  Mid-Layer 2 w8: v1(41163.39,43495) 41215.63,43547.24 41507.87,43547.24 41543.31,43511.81 42145.67,43511.81 42188.98,43555.12 42431.78,43555.12 v1(42488.05,43498.85)
CO9: TP53.1 U11.38 U12.5 | length 827.5
  Top Layer w8: U12.5@42494.09,42340.55 v1(42494.1,42397.69) ; v1(42494.09,42736.22) TP53.1@42530.28,42736.22 ; v1(42494.09,43074.75) U11.38@42494.09,43131.89
  Mid-Layer 2 w8: v1(42494.1,42397.69) v1(42494.09,43074.75)
CO10: TP55.1 U12.38 U13.5 | length 827.5
  Top Layer w8: U13.5@42494.09,41238.19 v1(42494.1,41295.33) ; v1(42494.09,41633.86) TP55.1@42530.28,41633.86 ; v1(42494.09,41972.39) U12.38@42494.09,42029.53
  Mid-Layer 2 w8: v1(42494.1,41295.33) v1(42494.09,41972.39)
CO11: TP57.1 U13.38 U14.5 | length 827.5
  Top Layer w8: U14.5@42494.09,40135.83 v1(42494.09,40192.97) ; v1(42494.09,40531.5) TP57.1@42530.28,40531.5 ; v1(42494.09,40870.02) U13.38@42494.09,40927.17
  Mid-Layer 2 w8: v1(42494.09,40192.97) v1(42494.09,40870.02)
CO12: TP59.1 U14.38 U15.5 | length 1254.4
  Top Layer w8: U14.38@42493.91,39825.61 42493.91,39776.09 v1(42495,39775) ; v1@43060.44,39774.8 TP59.1@43060.44,39810.98 ; v1(43623.83,39798.05) U15.5@43623.83,39825.61
  Mid-Layer 2 w8: v1(42495,39775) 42496.45,39773.55 43537.01,39773.55 43599.33,39773.55 v1(43623.83,39798.05)
  other v1: 43060,39773.55
CO13: TP75.1 U15.38 U16.5 | length 827.5
  Top Layer w8: TP75.1@43587.83,40531.5 v1(43624.02,40531.5) ; U15.38@43624.02,40135.83 v1(43624.02,40192.97) ; v1(43624.02,40870.02) U16.5@43624.02,40927.17
  Mid-Layer 2 w8: v1(43624.02,40192.97) v1(43624.02,40870.02)
CO14: TP77.1 U16.38 U17.5 | length 827.5
  Top Layer w8: TP77.1@43587.83,41633.86 v1(43624.02,41633.86) ; U16.38@43624.02,41238.19 v1(43624.02,41295.33) ; v1(43624.02,41972.39) U17.5@43624.02,42029.53
  Mid-Layer 2 w8: v1(43624.02,41295.33) v1(43624.02,41972.39)
CO15: TP79.1 U17.38 U18.5 | length 827.5
  Top Layer w8: TP79.1@43587.83,42736.22 v1(43624.02,42736.22) ; U17.38@43624.02,42340.55 v1(43624.02,42397.69) ; v1(43624.02,43074.75) U18.5@43624.02,43131.89
  Mid-Layer 2 w8: v1(43624.02,42397.69) v1(43624.02,43074.75)
CO16: TP73.1 U18.38 U19.5 | length 1553.5
  Top Layer w8: U18.38@43624.02,43442.91 v1(43624.02,43500.06) ; v1(44311.02,43511.81) TP73.1@44311.02,43547.99 ; U19.5@44954.72,43442.91 v1@44954.72,43495
  Mid-Layer 2 w8: v1(43624.02,43500.06) 43671.2,43547.24 43968.5,43547.24 44003.94,43511.81 44606.3,43511.81 44649.61,43555.12 44894.88,43555.12 v1(44955,43495)
CO17: TP93.1 U19.38 U20.5 | length 827.5
  Top Layer w8: U20.5@44954.72,42340.55 v1(44954.72,42397.69) ; v1(44954.72,42736.22) TP93.1@44990.91,42736.22 ; v1(44954.72,43074.75) U19.38@44954.72,43131.89
  Mid-Layer 2 w8: v1(44954.72,42397.69) v1(44954.72,43074.75)
CO18: TP95.1 U20.38 U21.5 | length 827.5
  Top Layer w8: U21.5@44954.72,41238.19 v1(44954.72,41295.33) ; v1(44954.72,41633.86) TP95.1@44990.91,41633.86 ; v1(44954.72,41975) U20.38@44954.72,42029.53
  Mid-Layer 2 w8: v1(44954.72,41295.33) v1(44954.72,41975)
CO19: TP97.1 U21.38 U22.5 | length 827.5
  Top Layer w8: U22.5@44954.72,40135.83 v1(44954.72,40192.97) ; v1(44954.72,40531.5) TP97.1@44990.91,40531.5 ; v1(44954.72,40870.02) U21.38@44954.72,40927.17
  Mid-Layer 2 w8: v1(44954.72,40192.97) v1(44954.72,40870.02)
CO20: TP99.1 U22.38 U23.5 | length 1265
  Top Layer w8: v1(44954.72,39768.65) U22.38@44954.72,39824.8 ; v1(45520,39765) TP99.1@45520,39801.18 ; v1(46084.46,39798.05) U23.5@46084.46,39825.61
  Mid-Layer 2 w8: v1(44954.72,39768.65) 44958.57,39764.8 46051.21,39764.8 46061.21,39774.8 v1(46084.46,39798.05)
CO21: TP113.1 U23.38 U24.5 | length 827.5
  Top Layer w8: TP113.1@46048.46,40531.5 v1(46084.65,40531.5) ; U23.38@46084.65,40135.83 v1(46084.65,40192.97) ; v1(46084.65,40870.02) U24.5@46084.65,40927.17
  Mid-Layer 2 w8: v1(46084.65,40192.97) v1(46084.65,40870.02)
CO22: TP115.1 U24.38 U25.5 | length 827.5
  Top Layer w8: TP115.1@46048.46,41633.86 v1(46084.65,41633.86) ; U24.38@46084.65,41238.19 v1(46084.65,41295.33) ; v1(46084.65,41972.39) U25.5@46084.65,42029.53
  Mid-Layer 2 w8: v1(46084.65,41295.33) v1(46084.65,41972.39)
CO23: TP117.1 U25.38 U26.5 | length 827.5
  Top Layer w8: TP117.1@46048.46,42736.22 v1(46084.65,42736.22) ; U25.38@46084.65,42340.55 v1(46084.65,42397.69) ; v1(46084.65,43074.75) U26.5@46084.65,43131.89
  Mid-Layer 2 w8: v1(46084.65,42397.69) v1(46084.65,43074.75)
CO24: TP119.1 U26.38 U27.5 | length 1556.1
  Top Layer w8: U26.38@46084.65,43442.91 v1(46084.65,43500.06) ; v1(46771.65,43511.81) TP119.1@46771.65,43547.99 ; U27.5@47415.35,43442.91 v1(47415.35,43500.06)
  Mid-Layer 2 w8: v1(46084.65,43500.06) 46131.83,43547.24 46429.13,43547.24 46464.57,43511.81 47066.93,43511.81 47110.24,43555.12 47360.29,43555.12 v1(47415.35,43500.06)
CO25: TP133.1 U27.38 U28.5 | length 827.5
  Top Layer w8: U28.5@47415.35,42340.55 v1(47415.35,42397.69) ; v1(47415.35,42736.22) TP133.1@47451.54,42736.22 ; v1(47415.35,43074.75) U27.38@47415.35,43131.89
  Mid-Layer 2 w8: v1(47415.35,42397.69) v1(47415.35,43074.75)
CO26: TP135.1 U28.38 U29.5 | length 827.5
  Top Layer w8: U29.5@47415.35,41238.19 v1(47415.36,41295.33) ; v1(47415.35,41633.86) TP135.1@47451.54,41633.86 ; v1(47415.35,41972.39) U28.38@47415.35,42029.53
  Mid-Layer 2 w8: v1(47415.36,41295.33) v1(47415.35,41972.39)
CO27: TP137.1 U29.38 U30.5 | length 827.5
  Top Layer w8: U30.5@47415.35,40135.83 v1(47415.35,40192.97) ; v1(47415.35,40531.5) TP137.1@47451.54,40531.5 ; v1(47415.35,40870.02) U29.38@47415.35,40927.17
  Mid-Layer 2 w8: v1(47415.35,40192.97) v1(47415.35,40870.02)
CO28: TP139.1 U30.38 U31.5 | length 1266.5
  Top Layer w8: v1(47415.17,39766.45) U30.38@47415.17,39825.61 ; v1(47980,39765) TP139.1@47980,39801.18 ; v1(48545.09,39798.05) U31.5@48545.09,39825.61
  Mid-Layer 2 w8: v1@47415.17,39765 48512.04,39765 v1(48545.09,39798.05)
CO29: TP152.1 U31.38 U32.5 | length 827.5
  Top Layer w8: TP152.1@48509.09,40531.5 v1(48545.28,40531.5) ; U31.38@48545.28,40135.83 v1(48545.28,40192.97) ; v1(48545.28,40870.02) U32.5@48545.28,40927.17
  Mid-Layer 2 w8: v1(48545.28,40192.97) v1(48545.28,40870.02)
CO30: TP154.1 U32.38 U33.5 | length 827.5
  Top Layer w8: TP154.1@48509.09,41633.86 v1(48545.28,41633.86) ; U32.38@48545.28,41238.19 v1(48545.28,41295.33) ; v1(48545.27,41972.39) U33.5@48545.28,42029.53
  Mid-Layer 2 w8: v1(48545.27,41972.39) v1(48545.28,41295.33)
CO31: TP156.1 U33.38 U34.5 | length 827.5
  Top Layer w8: TP156.1@48509.09,42736.22 v1(48545.28,42736.22) ; U33.38@48545.28,42340.55 v1(48545.28,42397.69) ; v1(48545.28,43074.75) U34.5@48545.28,43131.89
  Mid-Layer 2 w8: v1(48545.28,42397.69) v1(48545.28,43074.75)
EN1: R5.2 U1.2 | length 234.3
  Top Layer w11: R5.2@40093.53,43923 v1(40125,43923) ; U1.2@40172.05,44023.62 40208.38,44023.62 v1(40220,44012)
  Bottom Layer w11: v1(40125,43923) 40162,43923 40220,43981 v1(40220,44012)
EN2: R68.2 U41.2 | length 234.3
  Top Layer w11: R68.2@42436.05,43923 v1(42467.52,43923) ; U41.2@42514.57,44023.62 42550.9,44023.62 v1(42562.52,44012)
  Bottom Layer w11: v1(42467.52,43923) 42504.52,43923 42562.52,43981 v1(42562.52,44012)
EN3: R40.2 U37.2 | length 234.3
  Top Layer w11: R40.2@44880.93,43923 v1(44912.4,43923) ; U37.2@44959.45,44023.62 44995.78,44023.62 v1(45007.4,44012)
  Bottom Layer w11: v1(44912.4,43923) 44949.4,43923 45007.4,43981 v1(45007.4,44012)
EN4: R54.2 U39.2 | length 234.3
  Top Layer w11: R54.2@47235.26,43923 v1(47266.73,43923) ; U39.2@47313.78,44023.62 47350.11,44023.62 v1(47361.73,44012)
  Bottom Layer w11: v1(47266.73,43923) 47303.73,43923 47361.73,43981 v1(47361.73,44012)
FAN_PWM: J1.1 R27.2 | length 164.5
  Top Layer w15: R27.2@40384.53,45200 40450.04,45200 J1.1@40520.04,45130
FAN_SPEED: J1.2 R24.2 | length 308.8
  Top Layer w15: R24.2@40384.53,45140 40415,45140 40505,45050 40560,45050 40598.78,45088.78 J1.2@40598.78,45130
FANGND: C549.1 FAN1.1 FB35.1 FB36.1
